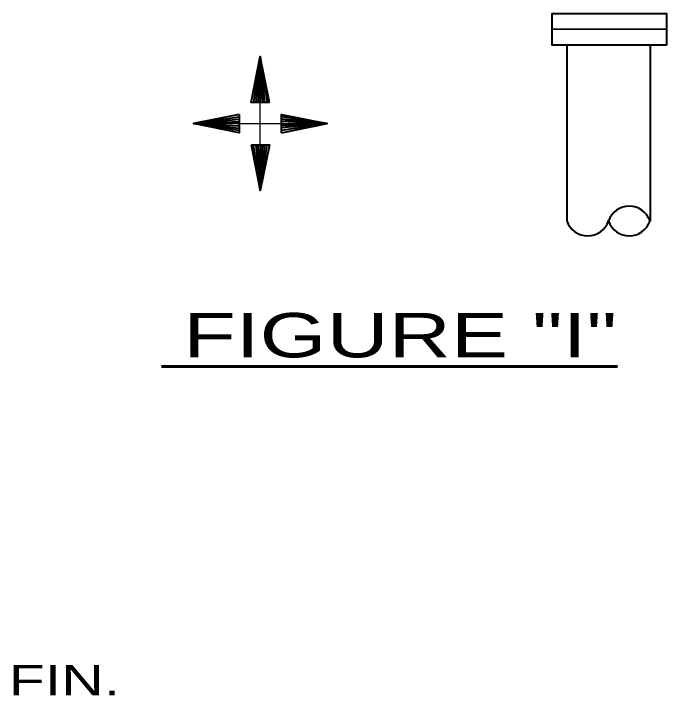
# Model space of a CAD drawing. Extents: x 55 to 190, y 198 to 264.
# Drawn here: x 79.22 to 84.67, y 213.54 to 219.23 of the extents above; entities that cross this region are included whole.
import ezdxf
from ezdxf.enums import TextEntityAlignment as Align

# ---------------------------------------------------------------- set-up
doc = ezdxf.new("R2010")
doc.units = 0
doc.header["$LTSCALE"] = 0.1
doc.layers.add('2', color=7, linetype='Continuous', lineweight=40)

msp = doc.modelspace()

# ---------------------------------------------------------------- linework, layer by layer
at = {"layer": '2', "lineweight": 35}
msp.add_line((83.7148, 219.1032), (84.6686, 219.1032), dxfattribs=at)
at = {"layer": '2'}
for p, q in [((83.8378, 218.9709), (83.8378, 217.5036)), ((84.5323, 218.9709), (84.5323, 217.5036)), ((81.278, 218.8752), (81.2219, 218.4928)), ((81.278, 218.8752), (81.2592, 218.4928)), ((81.2785, 218.4926), (81.278, 218.8752)), ((81.278, 218.8752), (81.3134, 218.4923)), ((81.278, 218.8752), (81.2962, 218.4928)), ((81.278, 218.8752), (81.3349, 218.4928)), ((80.7194, 218.3164), (81.1018, 218.3733)), ((81.8368, 218.3164), (81.4545, 218.3725)), ((80.7194, 218.3164), (81.1023, 218.3518)), ((80.7194, 218.3164), (81.1018, 218.3346)), ((81.102, 218.3169), (80.7194, 218.3164)), ((80.7194, 218.3164), (81.1018, 218.2603)), ((80.7194, 218.3164), (81.1018, 218.2976)), ((81.8368, 218.3164), (81.4539, 218.2809)), ((81.4542, 218.3158), (81.8368, 218.3164)), ((81.8368, 218.3164), (81.4545, 218.3352)), ((81.8368, 218.3164), (81.4545, 218.2981)), ((81.8368, 218.3164), (81.4545, 218.2595)), ((81.278, 217.7578), (81.2211, 218.1402)), ((81.278, 217.7578), (81.2425, 218.1407)), ((81.278, 217.7578), (81.2597, 218.1402)), ((81.2774, 218.1404), (81.278, 217.7578)), ((81.278, 217.7578), (81.3341, 218.1402)), ((81.278, 217.7578), (81.2968, 218.1402))]:
    msp.add_line(p, q, dxfattribs=at)
at = {"layer": '2', "lineweight": 25}
for p, q in [((81.278, 217.7578), (81.278, 218.8752)), ((80.7194, 218.3164), (81.8368, 218.3164))]:
    msp.add_line(p, q, dxfattribs=at)
at = {"layer": '2', "lineweight": 60}
msp.add_line((80.4519, 216.2881), (84.2601, 216.2881), dxfattribs=at)
at = {"layer": '2'}
msp.add_lwpolyline([(84.6686, 218.9709), (83.7148, 218.9709), (83.7148, 219.2339), (84.6686, 219.2339)], close=True, dxfattribs=at)
for points in [[(81.3542, 218.4928), (81.2012, 218.4931), (81.278, 218.8752)], [(81.3542, 218.4928), (81.278, 218.8752), (81.2404, 218.4926)], [(81.1018, 218.3926), (81.1015, 218.2396), (80.7194, 218.3164)], [(81.1018, 218.3926), (80.7194, 218.3164), (81.102, 218.2788)], [(81.4545, 218.2402), (81.4547, 218.3931), (81.8368, 218.3164)], [(81.4545, 218.2402), (81.8368, 218.3164), (81.4542, 218.3539)], [(81.2018, 218.1402), (81.278, 217.7578), (81.3155, 218.1404)], [(81.2018, 218.1402), (81.3547, 218.1399), (81.278, 217.7578)]]:
    msp.add_lwpolyline(points, dxfattribs=at)
for centre, start, end in [((84.3585, 217.4435), 19.0959, 160.9048), ((84.0114, 217.5636), 199.0959, 340.9048), ((84.3585, 217.5636), 199.0952, 340.9041)]:
    msp.add_arc(centre, 0.1837, start, end, dxfattribs=at)

# ---------------------------------------------------------------- texts
at = {"layer": '2', "width": 1.45}
msp.add_text('FIGURE "I"', height=0.3704, dxfattribs=at).set_placement((82.4456, 216.3651), align=Align.CENTER)
msp.add_text('FIN. ', height=0.254, dxfattribs=at).set_placement((79.1777, 213.5443))

doc.saveas('drawing.dxf')
